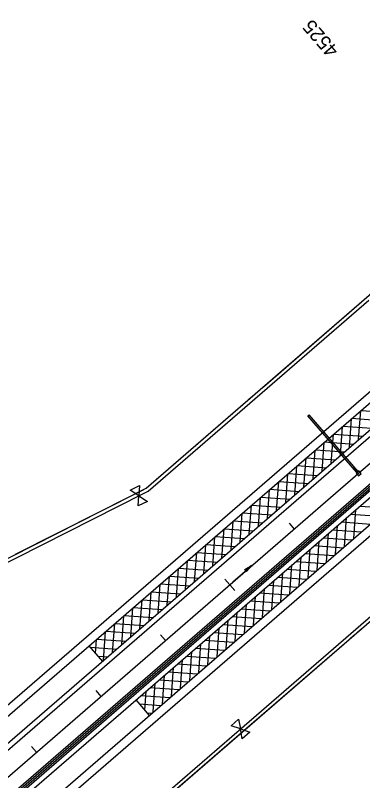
# Model space of a CAD drawing. Extents: x 192699 to 285914, y 194342 to 233219.
# Drawn here: x 201865 to 202273, y 201603 to 202501 of the extents above; entities that cross this region are included whole.
import ezdxf

# ---------------------------------------------------------------- set-up
doc = ezdxf.new("R2010")
doc.units = 0
for name, color, linetype in [('CENT LINE', 7, 'Continuous'), ('CONCRETE', 7, 'Continuous'), ('DRAINAGE', 7, 'Continuous'), ('DRAINAGE ARROWS', 7, 'Continuous'), ('PAVEMENT TRANSITION', 7, 'Continuous'), ('R-W - CofA', 7, 'Continuous'), ('R_Water Annot', 7, 'Continuous'), ('ROAD', 7, 'Continuous'), ('SHOULDER', 7, 'Continuous'), ('STATIONING1', 7, 'Continuous'), ('WRSF', 7, 'Continuous')]:
    doc.layers.add(name, color=color, linetype=linetype)

msp = doc.modelspace()

# ---------------------------------------------------------------- linework, layer by layer
at = {"layer": 'CENT LINE'}
msp.add_line((198833.18, 198989.86), (207514.58, 206505.51), dxfattribs=at)
at = {"layer": 'CONCRETE'}
for p, q in [((198844.96, 198976.25), (202641.48, 202262.97)), ((198847.58, 198973.23), (202644.1, 202259.95))]:
    msp.add_line(p, q, dxfattribs=at)
at = {"layer": 'DRAINAGE'}
for p, q in [((202267.58, 201965.73), (202209.98, 202032.26)), ((202266.07, 201964.42), (202208.47, 202030.95))]:
    msp.add_line(p, q, dxfattribs=at)
msp.add_lwpolyline([(202208.47, 202030.95), (202209.98, 202032.26)], dxfattribs=at)
msp.add_lwpolyline([(202267.93, 201960.74), (202270.95, 201963.36), (202268.33, 201966.38), (202265.31, 201963.77)], close=True, dxfattribs=at)
at = {"layer": 'DRAINAGE ARROWS'}
for p, q in [((202134.51, 201850.55), (202143.06, 201855.94)), ((202134.67, 201850.36), (202141.79, 201854.85)), ((202134.83, 201850.16), (202140.49, 201853.73)), ((202135, 201849.97), (202139.23, 201852.64)), ((202135.97, 201848.85), (202139.23, 201852.64)), ((202136.13, 201848.66), (202140.49, 201853.73)), ((202136.3, 201848.46), (202141.79, 201854.85)), ((202136.46, 201848.27), (202143.06, 201855.94)), ((202136.46, 201848.27), (202134.51, 201850.55)), ((202135.16, 201849.78), (202137.95, 201851.53)), ((202135.33, 201849.59), (202136.68, 201850.44)), ((202135.64, 201849.23), (202136.68, 201850.44)), ((202135.8, 201849.04), (202137.95, 201851.53))]:
    msp.add_line(p, q, dxfattribs=at)
at = {"layer": 'PAVEMENT TRANSITION'}
for p, q in [((202268.14, 202003.25), (202270.58, 202037.11)), ((202270.95, 202037.43), (202304.8, 202034.99)), ((202257.45, 201994), (202259.89, 202027.85)), ((202260.26, 202028.17), (202294.11, 202025.73)), ((202246.76, 201984.74), (202249.19, 202018.59)), ((202249.56, 202018.91), (202283.42, 202016.48)), ((202236.07, 201975.48), (202238.5, 202009.34)), ((202238.87, 202009.66), (202272.73, 202007.22)), ((202225.37, 201966.23), (202227.81, 202000.08)), ((202228.18, 202000.4), (202262.03, 201997.97)), ((202214.68, 201956.97), (202217.12, 201990.83)), ((202217.49, 201991.15), (202251.34, 201988.71)), ((202203.99, 201947.71), (202206.43, 201981.57)), ((202206.8, 201981.89), (202240.65, 201979.45)), ((202193.3, 201938.46), (202195.73, 201972.31)), ((202196.1, 201972.63), (202229.96, 201970.2)), ((202182.61, 201929.2), (202185.04, 201963.06)), ((202185.41, 201963.38), (202219.27, 201960.94)), ((202171.91, 201919.95), (202174.35, 201953.8)), ((202174.72, 201954.12), (202208.57, 201951.68)), ((202161.22, 201910.69), (202163.66, 201944.54)), ((202164.03, 201944.86), (202197.88, 201942.43)), ((202150.53, 201901.43), (202152.97, 201935.29)), ((202153.34, 201935.61), (202187.19, 201933.17)), ((202139.84, 201892.18), (202142.27, 201926.03)), ((202142.64, 201926.35), (202176.5, 201923.91)), ((202269.46, 201925.04), (202303.32, 201922.6)), ((202129.14, 201882.92), (202131.58, 201916.77)), ((202131.95, 201917.1), (202165.81, 201914.66)), ((202258.77, 201915.78), (202292.62, 201913.34)), ((202262.32, 201887.11), (202264.76, 201920.96)), ((202118.45, 201873.66), (202120.89, 201907.52)), ((202121.26, 201907.84), (202155.11, 201905.4)), ((202248.08, 201906.52), (202281.93, 201904.09)), ((202251.63, 201877.85), (202254.06, 201911.7)), ((202107.76, 201864.41), (202110.2, 201898.26)), ((202110.57, 201898.58), (202144.42, 201896.15)), ((202237.39, 201897.27), (202271.24, 201894.83)), ((202240.93, 201868.59), (202243.37, 201902.45)), ((202097.07, 201855.15), (202099.51, 201889.01)), ((202099.88, 201889.33), (202133.73, 201886.89)), ((202230.24, 201859.34), (202232.68, 201893.19)), ((202086.38, 201845.89), (202088.81, 201879.75)), ((202089.18, 201880.07), (202123.04, 201877.63)), ((202219.55, 201850.08), (202221.99, 201883.94)), ((202226.69, 201888.01), (202260.55, 201885.57)), ((202075.68, 201836.64), (202078.12, 201870.49)), ((202078.49, 201870.81), (202112.35, 201868.38)), ((202208.86, 201840.82), (202211.3, 201874.68)), ((202216, 201878.75), (202249.86, 201876.32)), ((202064.99, 201827.38), (202067.43, 201861.24)), ((202067.8, 201861.56), (202101.65, 201859.12)), ((202198.17, 201831.57), (202200.6, 201865.42)), ((202205.31, 201869.5), (202239.16, 201867.06)), ((202057.11, 201852.3), (202090.96, 201849.86)), ((202187.47, 201822.31), (202189.91, 201856.17)), ((202194.62, 201860.24), (202228.47, 201857.8)), ((202054.3, 201818.13), (202056.74, 201851.98)), ((202176.78, 201813.06), (202179.22, 201846.91)), ((202183.93, 201850.99), (202217.78, 201848.55)), ((202043.61, 201808.87), (202046.04, 201842.72)), ((202046.42, 201843.04), (202080.27, 201840.61)), ((202166.09, 201803.8), (202168.53, 201837.65)), ((202173.23, 201841.73), (202207.09, 201839.29)), ((202032.92, 201799.61), (202035.35, 201833.47)), ((202035.72, 201833.79), (202069.58, 201831.35)), ((202155.4, 201794.54), (202157.83, 201828.4)), ((202162.54, 201832.47), (202196.4, 201830.04)), ((202022.22, 201790.36), (202024.66, 201824.21)), ((202025.03, 201824.53), (202058.89, 201822.1)), ((202144.71, 201785.29), (202147.14, 201819.14)), ((202151.85, 201823.22), (202185.7, 201820.78)), ((202011.53, 201781.1), (202013.97, 201814.95)), ((202014.34, 201815.28), (202048.19, 201812.84)), ((202134.01, 201776.03), (202136.45, 201809.88)), ((202141.16, 201813.96), (202175.01, 201811.52)), ((202000.84, 201771.84), (202003.28, 201805.7)), ((202003.65, 201806.02), (202037.5, 201803.58)), ((202123.32, 201766.77), (202125.76, 201800.63)), ((202130.47, 201804.7), (202164.32, 201802.27)), ((201990.15, 201762.59), (201992.58, 201796.44)), ((201992.95, 201796.76), (202026.81, 201794.33)), ((202112.63, 201757.52), (202115.07, 201791.37)), ((202119.77, 201795.45), (202153.63, 201793.01)), ((201979.46, 201753.33), (201981.89, 201787.19)), ((201982.26, 201787.51), (202016.12, 201785.07)), ((202101.94, 201748.26), (202104.37, 201782.12)), ((202109.08, 201786.19), (202142.94, 201783.75)), ((201968.76, 201744.08), (201971.2, 201777.93)), ((201971.57, 201778.25), (202005.42, 201775.81)), ((202091.25, 201739.01), (202093.68, 201772.86)), ((202098.39, 201776.93), (202132.24, 201774.5)), ((201959.33, 201752.28), (201960.51, 201768.67)), ((201960.88, 201768.99), (201994.73, 201766.56)), ((202080.55, 201729.75), (202082.99, 201763.6)), ((202087.7, 201767.68), (202121.55, 201765.24)), ((201951.72, 201761.07), (201967.43, 201742.92)), ((201953.05, 201759.53), (201984.04, 201757.3)), ((202069.86, 201720.49), (202072.3, 201754.35)), ((202077.01, 201758.42), (202110.86, 201755.99)), ((201962.31, 201748.84), (201973.35, 201748.04)), ((202059.17, 201711.24), (202061.61, 201745.09)), ((202066.31, 201749.17), (202100.17, 201746.73)), ((202048.48, 201701.98), (202050.91, 201735.83)), ((202055.62, 201739.91), (202089.48, 201737.47)), ((202037.79, 201692.72), (202040.22, 201726.58)), ((202044.93, 201730.65), (202078.78, 201728.22)), ((202034.24, 201721.4), (202068.09, 201718.96)), ((202023.55, 201712.14), (202057.4, 201709.7)), ((202027.09, 201683.47), (202029.53, 201717.32)), ((202012.85, 201702.88), (202046.71, 201700.45)), ((202017.21, 201685.42), (202018.84, 201708.06)), ((202006.7, 201697.56), (202022.41, 201679.41)), ((202010.63, 201693.02), (202036.02, 201691.19)), ((202019.89, 201682.33), (202025.32, 201681.93))]:
    msp.add_line(p, q, dxfattribs=at)
at = {"layer": 'R-W - CofA'}
for p, q in [((202000.21, 201943.72), (202010.85, 201949.11)), ((202010.19, 201937.2), (202000.21, 201943.72)), ((202010.85, 201949.11), (202010.19, 201937.2)), ((202009.54, 201925.29), (202010.19, 201937.2)), ((202010.19, 201937.2), (202020.18, 201930.68)), ((202020.18, 201930.68), (202009.54, 201925.29)), ((202118.44, 201667.33), (202127.23, 201674.93)), ((202127.23, 201674.93), (202129.42, 201663.52)), ((202129.42, 201663.52), (202118.44, 201667.33)), ((202131.61, 201652.11), (202129.42, 201663.52)), ((202129.42, 201663.52), (202140.4, 201659.72)), ((202140.4, 201659.72), (202131.61, 201652.11))]:
    msp.add_line(p, q, dxfattribs=at)
for points in [[(198915, 198895.36), (200006.21, 199840.04), (200088.36, 199897.93), (200242.84, 200025.06), (200696.47, 200417.77), (200850.95, 200544.9), (200998.89, 200679.58), (203115.81, 202512.24), (203289.93, 202616.68), (203516.74, 202813.04), (203710.83, 203047.2)], [(198751.36, 199084.36), (199842.58, 200029.05), (200059.58, 200236.75), (200513.2, 200629.46), (200661.14, 200764.15), (200815.62, 200891.27), (201571.66, 201545.79), (201608, 201656.61), (201834.81, 201852.96), (202018.74, 201946.07), (202926, 202731.49), (203067.39, 202873.74)], [(202015.52, 201939.89), (202021.02, 201942.68), (202279.99, 202166.87)], [(202156.4, 202065.24), (202277.34, 202169.94)], [(202147.85, 202057.83), (202152.51, 202061.87)], [(202139.29, 202050.42), (202143.96, 202054.46)], [(202013.69, 201943.51), (202018.74, 201946.07), (202135.4, 202047.06)], [(201865.64, 201868.57), (202013.69, 201943.51)], [(201721.65, 201749.64), (201837.08, 201849.58), (202015.52, 201939.89)], [(202133.82, 201667.33), (202389.85, 201888.98)], [(202266.31, 201776.81), (202270.85, 201780.75)], [(202257.98, 201769.6), (202262.52, 201773.53)], [(202136.4, 201664.34), (202254.19, 201766.32)], [(201873.38, 201441.86), (202133.82, 201667.33)], [(202014.21, 201558.56), (202136.4, 201664.34)]]:
    msp.add_lwpolyline(points, dxfattribs=at)
at = {"layer": 'R_Water Annot'}
for p, q in [((202120.34, 201836.35), (202143.06, 201855.94)), ((202134.51, 201850.55), (202143.06, 201855.94)), ((202134.67, 201850.36), (202141.79, 201854.85)), ((202134.83, 201850.16), (202140.49, 201853.73)), ((202135, 201849.97), (202139.23, 201852.64)), ((202135.97, 201848.85), (202139.23, 201852.64)), ((202136.13, 201848.66), (202140.49, 201853.73)), ((202136.3, 201848.46), (202141.79, 201854.85)), ((202136.46, 201848.27), (202143.06, 201855.94)), ((202136.46, 201848.27), (202134.51, 201850.55)), ((202135.16, 201849.78), (202137.95, 201851.53)), ((202135.33, 201849.59), (202136.68, 201850.44)), ((202135.64, 201849.23), (202136.68, 201850.44)), ((202135.8, 201849.04), (202137.95, 201851.53))]:
    msp.add_line(p, q, dxfattribs=at)
at = {"layer": 'ROAD'}
for p, q in [((198797.83, 199030.68), (207479.24, 206546.34)), ((198813.54, 199012.54), (207494.94, 206528.19)), ((198852.81, 198967.18), (207534.22, 206482.83)), ((198868.52, 198949.03), (207549.92, 206464.68))]:
    msp.add_line(p, q, dxfattribs=at)
at = {"layer": 'SHOULDER'}
for p, q in [((198791.28, 199038.24), (202634.66, 202365.52)), ((198817.47, 199008), (202613.99, 202294.73)), ((198848.89, 198971.71), (202645.41, 202258.44)), ((198875.07, 198941.47), (202704.19, 202256.41))]:
    msp.add_line(p, q, dxfattribs=at)
at = {"layer": 'STATIONING1'}
for points in [[(202262.24, 201970.37), (202268.13, 201963.56)], [(202186.64, 201904.92), (202192.53, 201898.11)], [(202111.03, 201839.46), (202122.81, 201825.86)], [(202035.43, 201774.01), (202041.32, 201767.21)], [(201959.82, 201708.56), (201965.71, 201701.76)], [(201884.22, 201643.11), (201890.11, 201636.3)]]:
    msp.add_lwpolyline(points, dxfattribs=at)
at = {"layer": 'WRSF'}
msp.add_line((198846.27, 198974.74), (202676.77, 202290.88), dxfattribs=at)

# ---------------------------------------------------------------- texts
at = {"layer": 'STATIONING1'}
msp.add_text('4525', height=16.5, rotation=130.88334, dxfattribs=at).set_placement((202245.65, 202460.49))

doc.saveas('drawing.dxf')
